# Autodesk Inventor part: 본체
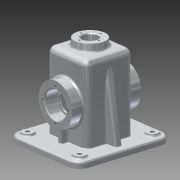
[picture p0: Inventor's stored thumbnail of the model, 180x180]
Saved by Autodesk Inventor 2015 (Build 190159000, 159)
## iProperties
Created: 2016-02
Part Number: 본체
Material: 알루미늄 6061
Document SubType Name: Modeling
Designer: Administrator
Density: 2.7 g/cm^3
Appearance: 알루미늄 - 평지
Mass: 799.07 g
Surface Area: 912.514 cm^2
Volume: 295.952 cm^3
Author: Administrator
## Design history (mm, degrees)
sketch "스케치1"
  geometry: L1 (-57.5, -65)-(57.5, -65); L2 (57.5, -65)-(57.5, 65); L3 (57.5, 65)-(-57.5, 65); L4 (-57.5, 65)-(-57.5, -65); L5 (-57.5, -65)-(57.5, 65); L6 (57.5, -65)-(-57.5, 65); 1 further point
  constraints: 12 end point, 2 midpoint, 2 parallel, 1 horizontal, 1 perpendicular
  dimensions: "d0" = 130 distance of L1.end L2.end; "d1" = 115 distance of L1.start L1.end
extrude "돌출1" new body sketch "스케치1" distance "d2" = 8; taper "d3" = 0 deg
sketch "스케치2"
  geometry: L1 (32.5, 32.5)-(-32.5, 32.5); L2 (-32.5, 32.5)-(-32.5, -32.5); L3 (-32.5, -32.5)-(32.5, -32.5); L4 (32.5, -32.5)-(32.5, 32.5); L5 (32.5, 32.5)-(-32.5, -32.5); L6 (-32.5, 32.5)-(32.5, -32.5); 1 further point
  constraints: 12 end point, 2 midpoint, 2 parallel, 1 horizontal, 1 perpendicular
  dimensions: "d4" = 65 distance of L1.end L2.end; "d5" = 65 distance of L1.start L1.end
extrude "돌출2" join sketch "스케치2" distance "d6" = 100; taper "d7" = 0 deg
sketch "스케치3"
  geometry: L1 (-52.5, -60)-(52.5, -60); L2 (52.5, -60)-(52.5, 60); L3 (52.5, 60)-(-52.5, 60); L4 (-52.5, 60)-(-52.5, -60); L5 (-52.5, -60)-(52.5, 60); L6 (52.5, -60)-(-52.5, 60); 1 further point
  constraints: 12 end point, 2 midpoint, 2 parallel, 1 horizontal, 1 perpendicular
  dimensions: "d8" = 120 distance of L1.end L2.end; "d9" = 105 distance of L1.start L1.end
extrude "돌출3" join sketch "스케치3" distance "d10" = 2; taper "d11" = 0 deg
sketch "스케치4"
  geometry: L1 (-20, -10)-(85, -10) reference; C1 r 27.5 at (32.5, 45); 1 further point
  constraints: 1 centre point, 1 vertical alignment
  dimensions: "d12" = 55 distance from line of L1 C1.centre; "d13" = 55 diameter of C1
extrude "돌출4" join sketch "스케치4" distance "d14" = 15; taper "d15" = 0 deg
sketch "스케치5"
  geometry: L1 (-20, -10)-(85, -10) reference; C1 r 27.5 at (32.5, 45); 1 further point
  constraints: 1 centre point, 1 vertical alignment
  dimensions: "d16" = 55 diameter of C1; "d17" = 55 distance from line of L1 C1.centre
extrude "돌출5" join sketch "스케치5" distance "d18" = 15; taper "d19" = 0 deg
sketch "스케치6"
  geometry: L1 (3, 42.5)-(-3, 42.5); L2 (-3, 42.5)-(-3, -42.5); L3 (-3, -42.5)-(3, -42.5); L4 (3, -42.5)-(3, 42.5); L5 (3, 42.5)-(-3, -42.5); L6 (-3, 42.5)-(3, -42.5); 1 further point
  constraints: 12 end point, 2 midpoint, 2 parallel, 1 horizontal, 1 perpendicular
  dimensions: "d20" = 6 distance of L1.start L1.end; "d21" = 85 distance of L1.end L2.end
extrude "돌출6" join sketch "스케치6" distance "d22" = 25; taper "d23" = 0 deg
sketch "스케치8"
  geometry: L1 (-32.5, 8)-(-32.5, 108) reference; L2 (32.5, 8)-(32.5, 108) reference; L3 (-47.5, 8)-(-32.5, 93.069); L4 (32.5, 93.069)-(47.5, 8); L5 (57.5, 8)-(-57.5, 8) reference; L6 (-47.5, 8)-(47.5, 8); L7 (-32.5, 93.069)-(32.5, 93.069); 1 further point
  constraints: 8 end point, 3 point on line, 2 horizontal
  dimensions: "d28" = 10 distance of L3.start L5.end; "d29" = 10 distance of L5.start L4.end; "d30" = 80 deg angle of L5 L4
extrude "돌출7" join sketch "스케치8" stored distance "d31" = 10; taper "d32" = 0 deg
sketch "스케치10"
  geometry: L1 (-27.5, -27.5)-(27.5, -27.5); L2 (27.5, -27.5)-(27.5, 27.5); L3 (27.5, 27.5)-(-27.5, 27.5); L4 (-27.5, 27.5)-(-27.5, -27.5); L5 (-27.5, -27.5)-(27.5, 27.5); L6 (27.5, -27.5)-(-27.5, 27.5); 1 further point
  constraints: 12 end point, 2 midpoint, 2 parallel, 1 horizontal, 1 perpendicular
  dimensions: "d36" = 55 distance of L1.end L2.end; "d37" = 55 distance of L1.start L1.end
extrude "돌출9" cut sketch "스케치10" distance "d38" = 105; taper "d39" = 0 deg
sketch "스케치11"
  geometry: L1 (52.5, -53)-(-52.5, -53) reference; C1 r 17.5 at (0, 0); 1 further point
  constraints: 1 centre point, 1 vertical alignment
  dimensions: "d40" = 35 diameter of C1; "d41" = 53 distance from line of L1 C1.centre
extrude "돌출10" cut sketch "스케치11" distance "d42" = 17; taper "d43" = 0 deg
sketch "스케치12"
  geometry: L1 (-27.5, -55)-(27.5, -55) reference; C1 r 17.5 at (0, 0); 1 further point
  constraints: 1 centre point, 1 vertical alignment
  dimensions: "d44" = 35 diameter of C1; "d45" = 55 distance from line of L1 C1.centre
extrude "돌출11" cut sketch "스케치12" distance "d46" = 17; taper "d47" = 0 deg
sketch "스케치13"
  geometry: L1 (-27.5, -55)-(27.5, -55) reference; L2 (52.5, -53)-(-52.5, -53) reference; C1 r 15 at (0, 0); 2 further points
  constraints: 1 centre point, 1 midpoint, 1 vertical alignment
  dimensions: "d48" = 55 distance from line of L1 C1.centre; "d49" = 30 diameter of C1
extrude "돌출12" cut sketch "스케치13" stored distance "d50" = 17; taper "d51" = 0 deg
node "작업 평면4"
sketch "스케치16"
  geometry: C1 r 20 at (0, 0); 1 further point
  constraints: 1 centre point, 1 coincident
  dimensions: "d58" = 40 diameter of C1
extrude "돌출14" join sketch "스케치16" stored distance "d59" = 17; taper "d60" = 5 deg
sketch "스케치17"
  geometry: C1 r 10.5 at (0, 0); 1 further point
  constraints: 1 centre point, 1 coincident
  dimensions: "d61" = 21 diameter of C1
extrude "돌출15" cut sketch "스케치17" stored distance "d62" = 17; taper "d63" = 0 deg
sketch "스케치18"
  geometry: L1 (52.5, -55)-(-52.5, -55) reference; 2 further points
  constraints: 1 vertical alignment
  dimensions: "d64" = 76 distance from line of L1 point (0, 21)
hole "구멍1" sketch "스케치18" at (0, 21) diameter "d65" = 3.242; stored, may be unused: countersink angle "d69" = 90 deg, drill point angle "d71" = 118 deg; dims "d66" = 8, "d67" = 4, "d68" = 2, "d70" = 10
sketch "스케치19"
  geometry: C1 r 1.621 at (0, 21) reference; 2 further points
  constraints: 1 coincident
hole "구멍2" sketch "스케치19" at (0, 21) diameter "d75" = 3.242; stored, may be unused: countersink angle "d79" = 90 deg, drill point angle "d81" = 118 deg; dims "d76" = 8, "d77" = 4, "d78" = 2, "d80" = 10
sketch "스케치20"
  geometry: 2 further points
  constraints: 1 horizontal alignment
  dimensions: "d85" = 14.5 distance of point (-14.5, 0) point (0, 0)
hole "구멍3" sketch "스케치20" at (-14.5, 0) diameter "d86" = 2.459; stored, may be unused: countersink angle "d90" = 90 deg, drill point angle "d92" = 118 deg; dims "d87" = 7, "d88" = 4, "d89" = 2, "d91" = 9
sketch "스케치22"
  geometry: L1 (-57.5, 65)-(-57.5, -65) reference; L2 (-57.5, -65)-(57.5, -65) reference; C1 r 7.5 at (-42.5, -50); C2 r 7.5 at (-42.5, 50); C3 r 7.5 at (42.5, -50); C4 r 7.5 at (42.5, 50); 1 further point
  constraints: 4 centre point, 1 horizontal, 1 vertical, 6 other
  dimensions: "d109" = 15 distance from line of L1 C1.centre; "d110" = 15 distance from line of L2 C1.centre; "d111" = 15 diameter of C1; "d114" = 100 distance of C1.centre C2.centre; "d117" = 85 distance of C1.centre C3.centre
extrude "돌출17" join sketch "스케치22" distance "d120" = 3; taper "d121" = 0 deg
sketch "스케치23"
  geometry: L1 (52.5, 60)-(-52.5, 60) reference; L2 (-52.5, 60)-(-52.5, -60) reference; C1 r 3 at (-42.5, 50); C2 r 3 at (42.5, 50); C3 r 3 at (-42.5, -50); C4 r 3 at (42.5, -50); 1 further point
  constraints: 4 centre point, 1 horizontal, 1 vertical, 6 other
  dimensions: "d122" = 10 distance from line of L1 C1.centre; "d123" = 10 distance from line of L2 C1.centre; "d124" = 6 diameter of C1; "d127" = 85 distance of C1.centre C2.centre; "d130" = 100 distance of C1.centre C3.centre
extrude "돌출18" cut sketch "스케치23" stored distance "d133" = 3; taper "d134" = 0 deg
fillet "모깎기1" dims "d135" = 8
fillet "모깎기2" dims "d136" = 15
fillet "모깎기3" dims "d137" = 0.3
fillet "모깎기4" dims "d138" = 10
fillet "모깎기5" dims "d139" = 3
fillet "모깎기9" dims "d143" = 3
fillet "모깎기10" dims "d144" = 3
fillet "모깎기11" dims "d145" = 3
fillet "모깎기12" dims "d146" = 3
fillet "모깎기13" dims "d147" = 8
fillet "모깎기14" dims "d148" = 3
fillet "모깎기15" dims "d149" = 3
fillet "모깎기16" dims "d150" = 3
fillet "모깎기17" dims "d151" = 1
chamfer "모따기1" distance "d152" = 1; stored, may be unused: second distance "d153" = 2, angle "d154" = 45 deg
fillet "모깎기18" dims "d155" = 3
fillet "모깎기19" dims "d156" = 3
node "작업 평면5"
sketch "스케치24"
  geometry: L1 (-20, 118)-(20, 118) reference; L2 (32.5, 9)-(32.5, 100) reference; 2 further points
  constraints: 1 other
  dimensions: "d158" = 26 distance from line of point (0, 92) L1; "d159" = 32.5 distance from line of L2 point (0, 92)
feature "엠보싱1" sketch "스케치24" dims "d8" = 120, "d9" = 105, "d160" = 0.5, "d161" = 0
fillet "모깎기20" dims "d162" = 3
node "솔리드1"
pattern_circular "원형 패턴1" dims angle "d73" = 360 deg
pattern_circular "원형 패턴2" dims angle "d83" = 360 deg
pattern_circular "원형 패턴3" dims angle "d94" = 360 deg
other parameters: "d57" = 118, "d157" = -35
